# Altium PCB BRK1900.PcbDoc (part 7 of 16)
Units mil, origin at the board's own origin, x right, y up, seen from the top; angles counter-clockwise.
Board outline 8858.27 x 5905.51 mil, 10 copper layers (L1-TOP, L2-GND, L3-PWR, L4-GND, L5-PWR, L6-PWR, L7-GND, L8-SIG, L9-GND, L10-BOT), stack 48.824 mil thick; 456 components, 571 nets, 2296 pads, 2416 vias.
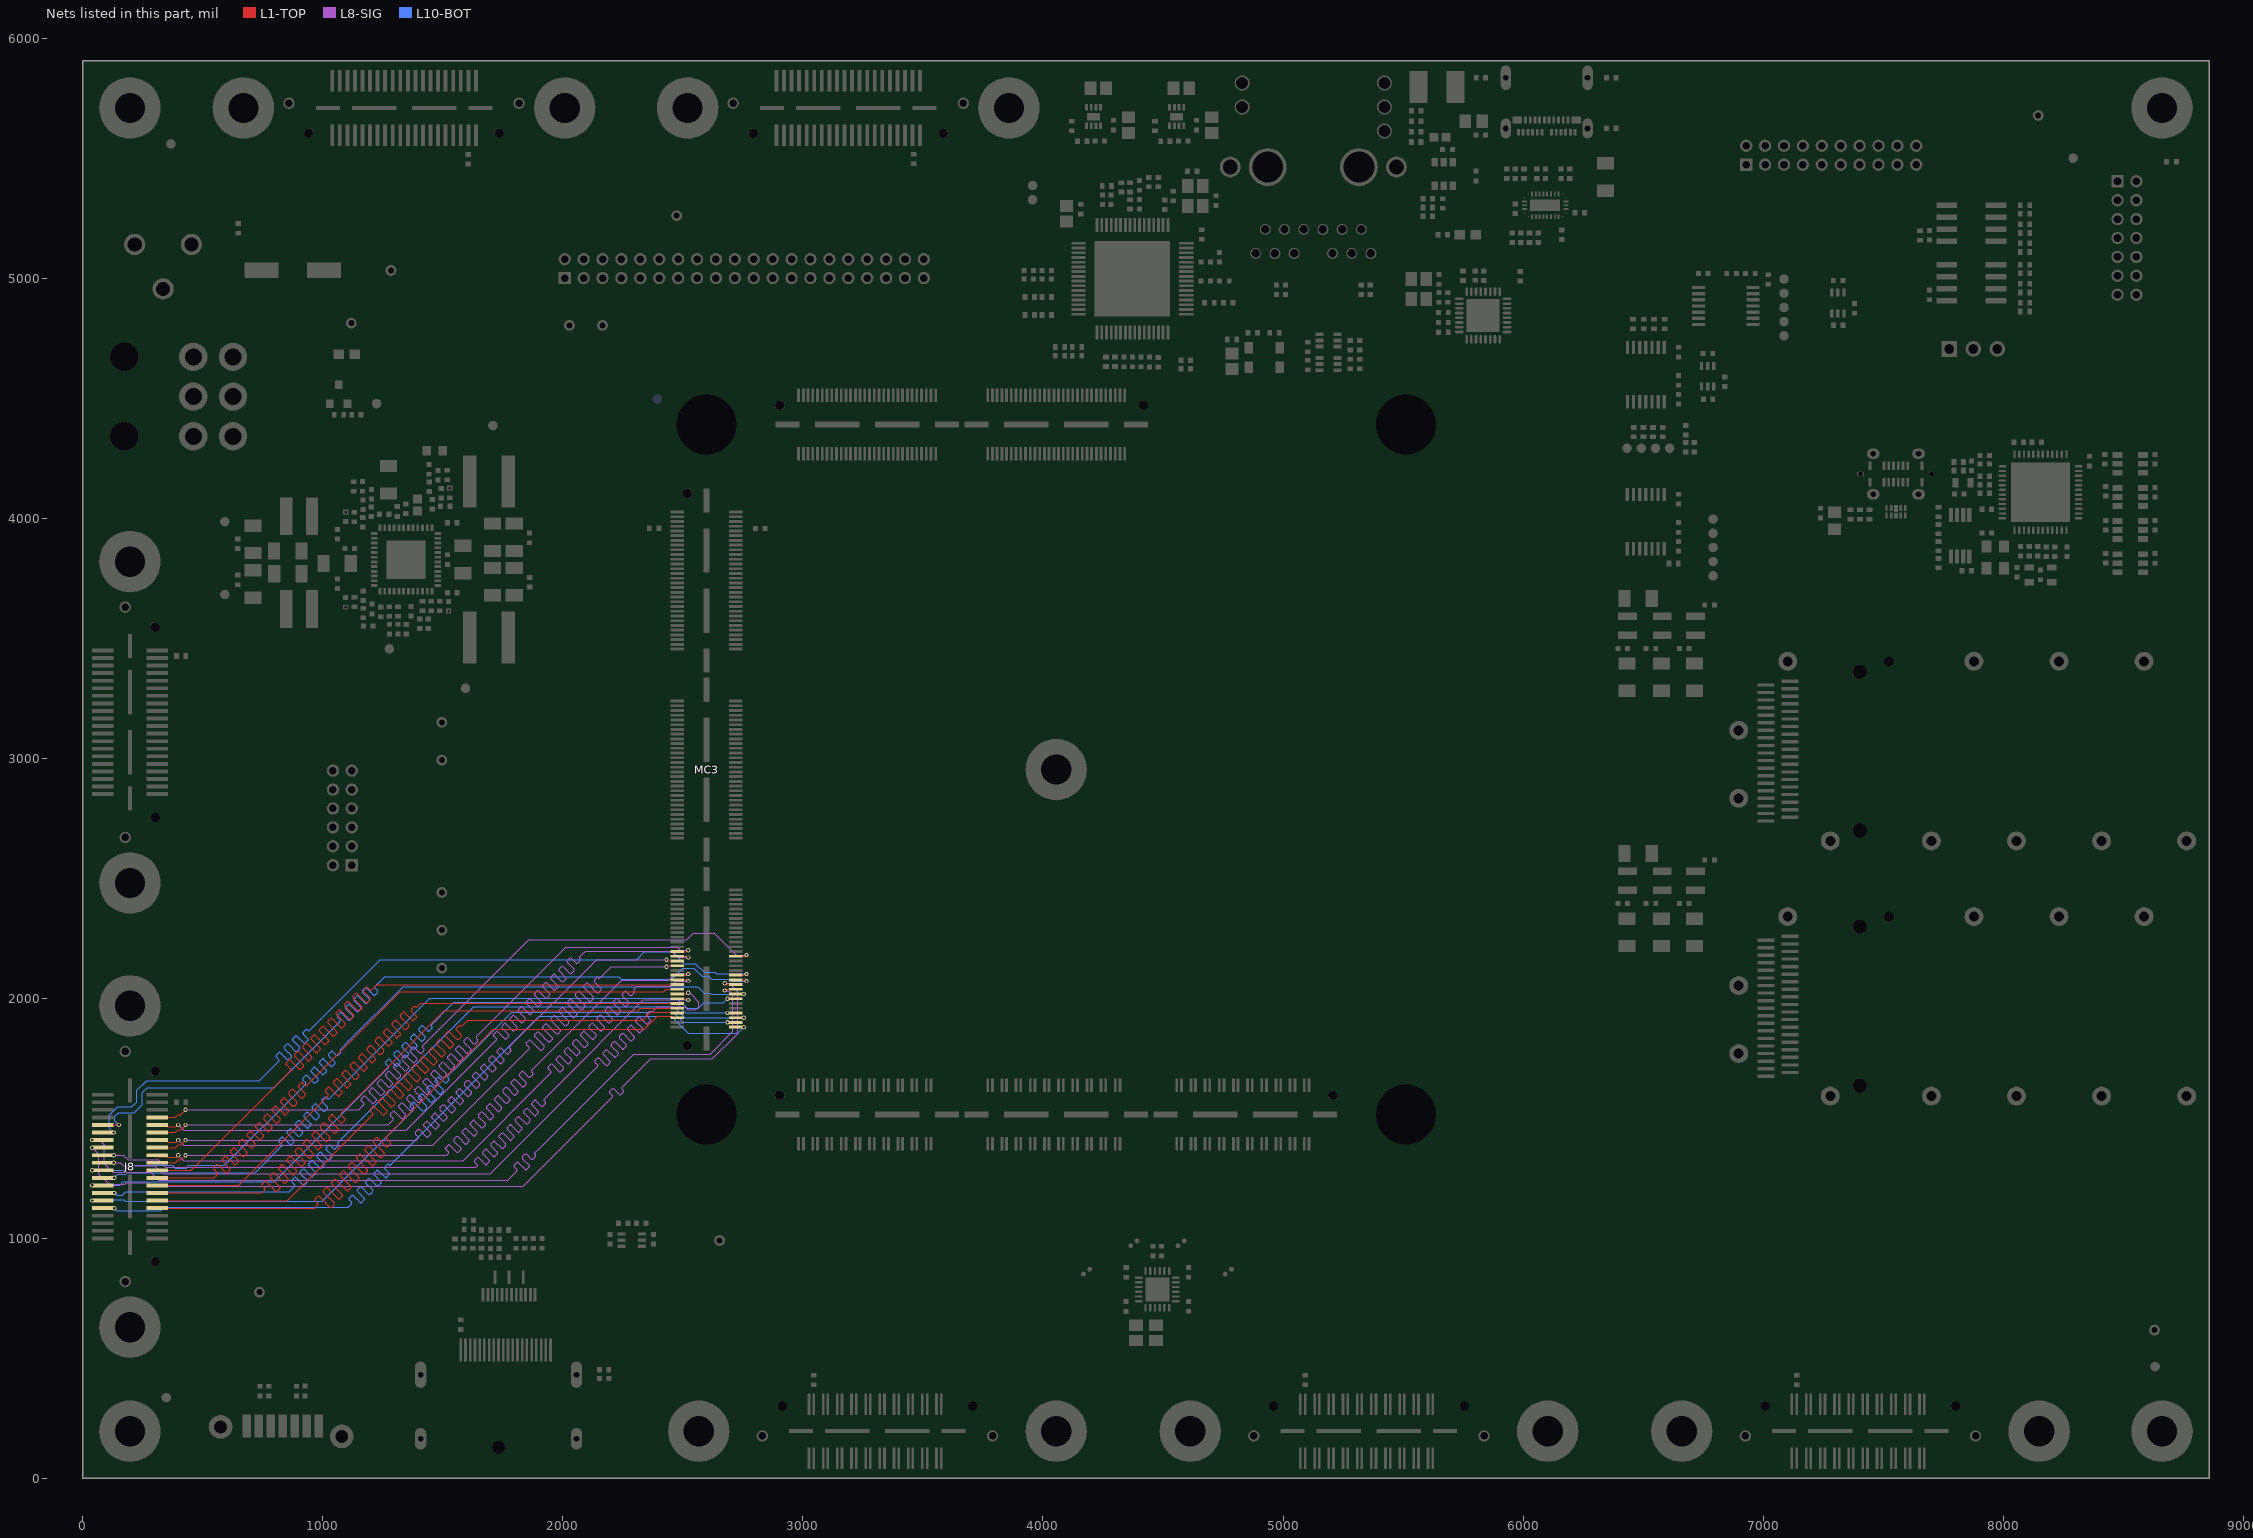
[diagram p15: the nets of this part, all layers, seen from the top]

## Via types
v1: diameter 18, hole 10, L1-TOP to L10-BOT, tented both sides, 2170 vias
v2: diameter 20, hole 10, L1-TOP to L10-BOT, tented both sides, 246 vias

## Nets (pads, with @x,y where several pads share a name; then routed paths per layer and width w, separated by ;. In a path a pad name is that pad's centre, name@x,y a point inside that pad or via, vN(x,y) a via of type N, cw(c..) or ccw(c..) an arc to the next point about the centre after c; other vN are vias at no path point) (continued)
SZG_PORTA_S3: J8.8 MC3.32 | length 3481.2
  L1-TOP w4.55: J8.8@309.65,1504.01 386.17,1504.01 397.91,1515.75 409,1515.75 428.26,1535 v1(428.26,1535.51) ; MC3.32@2720.08,2175.2 2756.5,2175.2 2761.44,2180.13 v1(2765.08,2180.13)
  L8-SIG w4.05: v1(428.26,1535.51) 1149.68,1535.51 1169.29,1555.12 1170.72,1556.55 ccw(c1167.32,1559.95) 1170.72,1563.35 1159.85,1574.23 cw(c1163.25,1577.63) 1159.85,1581.03 1170.05,1591.23 cw(c1173.45,1587.83) 1176.85,1591.23 1205.41,1562.68 ccw(c1208.81,1566.08) 1212.21,1562.68 1222.41,1572.88 ccw(c1219.01,1576.29) 1222.41,1579.69 1193.86,1608.24 cw(c1197.26,1611.64) 1193.86,1615.04 1204.06,1625.25 cw(c1207.46,1621.84) 1210.87,1625.25 1239.42,1596.69 ccw(c1242.82,1600.09) 1246.22,1596.69 1256.42,1606.9 ccw(c1253.02,1610.3) 1256.42,1613.7 1227.87,1642.25 cw(c1231.27,1645.65) 1227.87,1649.05 1238.08,1659.26 cw(c1241.48,1655.86) 1244.88,1659.26 1273.43,1630.7 ccw(c1276.83,1634.11) 1280.23,1630.7 1290.44,1640.91 ccw(c1287.04,1644.31) 1290.44,1647.71 1261.88,1676.26 cw(c1265.28,1679.66) 1261.88,1683.07 1272.09,1693.27 cw(c1275.49,1689.87) 1278.89,1693.27 1307.44,1664.72 ccw(c1310.84,1668.12) 1314.24,1664.72 1324.45,1674.92 ccw(c1321.05,1678.32) 1324.45,1681.72 1295.9,1710.28 cw(c1299.3,1713.68) 1295.9,1717.08 1306.1,1727.28 cw(c1309.5,1723.88) 1312.9,1727.28 1341.45,1698.73 ccw(c1344.86,1702.13) 1348.26,1698.73 1358.46,1708.93 ccw(c1355.06,1712.33) 1358.46,1715.73 1329.91,1744.29 cw(c1333.31,1747.69) 1329.91,1751.09 1340.11,1761.29 cw(c1343.51,1757.89) 1346.91,1761.29 1375.47,1732.74 ccw(c1378.87,1736.14) 1382.27,1732.74 1392.47,1742.94 ccw(c1389.07,1746.34) 1392.47,1749.75 1363.92,1778.3 cw(c1367.32,1781.7) 1363.92,1785.1 1374.12,1795.3 cw(c1377.52,1791.9) 1380.93,1795.3 1404.18,1772.05 ccw(c1407.58,1775.45) 1410.98,1772.05 1421.18,1782.26 ccw(c1417.78,1785.66) 1421.18,1789.06 1415.61,1794.63 cw(c1419.01,1798.03) 1415.61,1801.44 1477.11,1862.94 1858.27,2244.09 2515.75,2244.09 2542.65,2271 2630.57,2271 2721.44,2180.13 v1(2765.08,2180.13)
SZG_PORTA_S4: J8.9 MC3.22 | length 3464.4
  L1-TOP w4.55: J8.9@84.05,1472.51 84.12,1472.44 v1(149.61,1472.44) ; MC3.22@2720.08,2076.77 2756.4,2076.77 2761.44,2071.74 v1(2765.08,2071.74)
  L10-BOT w4.55: v1(149.61,1472.44) 133.86,1488.19 133.86,1507.87 149.61,1523.62 214.51,1523.62 248.03,1557.14 248.03,1606.3 269.75,1628.01 796.32,1628.01 1070.37,1902.07 1071.98,1903.68 ccw(c1068.51,1907.15) 1071.98,1910.62 1061.25,1921.35 cw(c1064.72,1924.83) 1061.25,1928.3 1071.66,1938.71 cw(c1075.14,1935.24) 1078.61,1938.71 1107.02,1910.3 ccw(c1110.49,1913.77) 1113.96,1910.3 1124.38,1920.72 ccw(c1120.91,1924.19) 1124.38,1927.66 1095.97,1956.07 cw(c1099.44,1959.54) 1095.97,1963.02 1106.38,1973.43 cw(c1109.86,1969.96) 1113.33,1973.43 1141.74,1945.02 ccw(c1145.21,1948.49) 1148.68,1945.02 1159.1,1955.44 ccw(c1155.63,1958.91) 1159.1,1962.38 1130.69,1990.79 cw(c1134.16,1994.26) 1130.69,1997.74 1141.1,2008.15 cw(c1144.57,2004.68) 1148.05,2008.15 1176.46,1979.74 ccw(c1179.93,1983.21) 1183.4,1979.74 1193.82,1990.16 ccw(c1190.35,1993.63) 1193.82,1997.1 1165.41,2025.51 cw(c1168.88,2028.98) 1165.41,2032.45 1175.82,2042.87 cw(c1179.29,2039.4) 1182.77,2042.87 1210.98,2014.66 ccw(c1214.45,2018.13) 1217.92,2014.66 1228.34,2025.07 ccw(c1224.87,2028.54) 1228.34,2032.02 1217.8,2042.55 cw(c1221.27,2046.02) 1217.8,2049.5 1255.41,2087.11 1258.86,2090.55 2232.28,2090.55 2244.09,2078.74 2452.76,2078.74 2500,2125.98 2545.72,2125.98 2580.92,2090.79 2607.32,2090.79 2618.96,2079.14 2696.45,2079.14 2703.86,2071.74 v1(2765.08,2071.74)
SZG_PORTA_S5: J8.10 MC3.31 | length 3483.8
  L1-TOP w4.55: J8.10@309.65,1472.51 315.38,1466.79 352.13,1466.79 355,1463.91 389.63,1463.91 v1(398.23,1472.51) ; MC3.31@2476.77,2175.2 2513.09,2175.2 2518.13,2170.16 v1(2521.77,2170.16)
  L8-SIG w4.05: v1@398.23,1472.76 420.43,1450.57 1348.2,1450.57 1721.55,1823.91 1722.98,1825.34 ccw(c1719.58,1828.74) 1722.98,1832.15 1712.11,1843.02 cw(c1715.51,1846.42) 1712.11,1849.82 1722.31,1860.03 cw(c1725.71,1856.63) 1729.11,1860.03 1757.67,1831.47 ccw(c1761.07,1834.88) 1764.47,1831.47 1774.67,1841.68 ccw(c1771.27,1845.08) 1774.67,1848.48 1746.12,1877.03 cw(c1749.52,1880.43) 1746.12,1883.84 1756.32,1894.04 cw(c1759.72,1890.64) 1763.12,1894.04 1791.68,1865.49 ccw(c1795.08,1868.89) 1798.48,1865.49 1808.68,1875.69 ccw(c1805.28,1879.09) 1808.68,1882.49 1780.13,1911.05 cw(c1783.53,1914.45) 1780.13,1917.85 1790.33,1928.05 cw(c1793.73,1924.65) 1797.14,1928.05 1825.69,1899.5 ccw(c1829.09,1902.9) 1832.49,1899.5 1842.69,1909.7 ccw(c1839.29,1913.1) 1842.69,1916.5 1814.14,1945.06 cw(c1817.54,1948.46) 1814.14,1951.86 1824.35,1962.06 cw(c1827.75,1958.66) 1831.15,1962.06 1859.7,1933.51 ccw(c1863.1,1936.91) 1866.5,1933.51 1876.71,1943.71 ccw(c1873.31,1947.11) 1876.71,1950.52 1848.15,1979.07 cw(c1851.55,1982.47) 1848.15,1985.87 1858.36,1996.07 cw(c1861.76,1992.67) 1865.16,1996.07 1893.71,1967.52 ccw(c1897.11,1970.92) 1900.51,1967.52 1910.72,1977.73 ccw(c1907.32,1981.13) 1910.72,1984.53 1882.17,2013.08 cw(c1885.57,2016.48) 1882.17,2019.88 1892.37,2030.09 cw(c1895.77,2026.69) 1899.17,2030.09 1927.72,2001.53 ccw(c1931.13,2004.93) 1934.53,2001.53 1944.73,2011.74 ccw(c1941.33,2015.14) 1944.73,2018.54 1916.18,2047.09 cw(c1919.58,2050.49) 1916.18,2053.89 1926.38,2064.1 cw(c1929.78,2060.7) 1933.18,2064.1 1961.74,2035.55 ccw(c1965.14,2038.95) 1968.54,2035.55 1978.74,2045.75 ccw(c1975.34,2049.15) 1978.74,2052.55 1950.19,2081.1 cw(c1953.59,2084.51) 1950.19,2087.91 1960.39,2098.11 cw(c1963.79,2094.71) 1967.19,2098.11 1995.75,2069.56 ccw(c1999.15,2072.96) 2002.55,2069.56 2012.75,2079.76 ccw(c2009.35,2083.16) 2012.75,2086.56 1984.2,2115.12 cw(c1987.6,2118.52) 1984.2,2121.92 1994.4,2132.12 cw(c1997.81,2128.72) 2001.21,2132.12 2029.76,2103.57 ccw(c2033.16,2106.97) 2036.56,2103.57 2046.77,2113.77 ccw(c2043.36,2117.17) 2046.77,2120.57 2018.21,2149.13 cw(c2021.61,2152.53) 2018.21,2155.93 2028.42,2166.13 cw(c2031.82,2162.73) 2035.22,2166.13 2054.86,2146.49 ccw(c2058.26,2149.89) 2061.66,2146.49 2071.87,2156.69 ccw(c2068.47,2160.1) 2071.87,2163.5 2069.9,2165.46 cw(c2073.3,2168.86) 2069.9,2172.26 2082.68,2185.04 2094.49,2196.85 2452.76,2196.85 2479.45,2170.16 v1(2521.77,2170.16)
SZG_PORTA_S6: J8.11 MC3.24 | length 3419.8
  L1-TOP w4.55: MC3.24@2720.08,2096.46 2756.5,2096.46 2761.44,2101.39 v1(2765.08,2101.39)
  L10-BOT w4.55: v1(128.76,1441.01) 110.24,1459.53 110.24,1511.81 145.67,1547.24 204.72,1547.24 224.41,1566.93 224.41,1616.08 265.81,1657.48 736.22,1657.48 814.96,1736.22 816.57,1737.83 ccw(c813.1,1741.3) 816.57,1744.77 805.84,1755.51 cw(c809.31,1758.98) 805.84,1762.45 816.25,1772.87 cw(c819.72,1769.39) 823.2,1772.87 851.61,1744.46 ccw(c855.08,1747.93) 858.55,1744.46 868.97,1754.87 ccw(c865.49,1758.34) 868.97,1761.81 840.55,1790.23 cw(c844.03,1793.7) 840.55,1797.17 850.97,1807.59 cw(c854.44,1804.11) 857.91,1807.59 886.33,1779.17 ccw(c889.8,1782.65) 893.27,1779.17 903.69,1789.59 ccw(c900.21,1793.06) 903.69,1796.53 875.27,1824.95 cw(c878.75,1828.42) 875.27,1831.89 885.69,1842.3 cw(c889.16,1838.83) 892.63,1842.3 921.04,1813.89 ccw(c924.52,1817.36) 927.99,1813.89 938.4,1824.31 ccw(c934.93,1827.78) 938.4,1831.25 919.08,1850.58 cw(c922.55,1854.05) 919.08,1857.52 929.49,1867.94 cw(c932.96,1864.47) 936.44,1867.94 938.09,1866.29 ccw(c941.56,1869.76) 945.03,1866.29 980.32,1901.57 1240.16,2161.42 2307.09,2161.42 2338.58,2192.91 2458.17,2192.91 2506.28,2144.8 2552.05,2144.8 2589.13,2107.72 2632.27,2107.72 2638.6,2101.39 v1(2765.08,2101.39)
SZG_PORTA_S7: J8.12 MC3.33 | length 3480.9
  L1-TOP w4.55: J8.12@309.65,1441.01 386.17,1441.01 397.91,1452.75 409,1452.75 428.26,1472 v1(428.26,1472.51) ; MC3.33@2476.77,2194.88 2513.19,2194.88 2518.13,2199.82 v1(2521.77,2199.82)
  L8-SIG w4.05: v1@428.26,1472.76 1271.97,1472.76 1291.34,1492.13 1292.77,1493.56 ccw(c1289.37,1496.96) 1292.77,1500.36 1281.9,1511.24 cw(c1285.3,1514.64) 1281.9,1518.04 1292.1,1528.24 cw(c1295.5,1524.84) 1298.9,1528.24 1327.45,1499.69 ccw(c1330.86,1503.09) 1334.26,1499.69 1344.46,1509.89 ccw(c1341.06,1513.29) 1344.46,1516.69 1315.91,1545.25 cw(c1319.31,1548.65) 1315.91,1552.05 1326.11,1562.25 cw(c1329.51,1558.85) 1332.91,1562.25 1361.47,1533.7 ccw(c1364.87,1537.1) 1368.27,1533.7 1378.47,1543.9 ccw(c1375.07,1547.31) 1378.47,1550.71 1349.92,1579.26 cw(c1353.32,1582.66) 1349.92,1586.06 1360.12,1596.27 cw(c1363.52,1592.86) 1366.93,1596.27 1395.48,1567.71 ccw(c1398.88,1571.11) 1402.28,1567.71 1412.48,1577.92 ccw(c1409.08,1581.32) 1412.48,1584.72 1383.93,1613.27 cw(c1387.33,1616.67) 1383.93,1620.07 1394.13,1630.28 cw(c1397.54,1626.88) 1400.94,1630.28 1429.49,1601.72 ccw(c1432.89,1605.13) 1436.29,1601.72 1446.5,1611.93 ccw(c1443.09,1615.33) 1446.5,1618.73 1417.94,1647.28 cw(c1421.34,1650.68) 1417.94,1654.09 1428.15,1664.29 cw(c1431.55,1660.89) 1434.95,1664.29 1463.5,1635.74 ccw(c1466.9,1639.14) 1470.3,1635.74 1480.51,1645.94 ccw(c1477.11,1649.34) 1480.51,1652.74 1451.95,1681.3 cw(c1455.36,1684.7) 1451.95,1688.1 1462.16,1698.3 cw(c1465.56,1694.9) 1468.96,1698.3 1497.51,1669.75 ccw(c1500.91,1673.15) 1504.32,1669.75 1514.52,1679.95 ccw(c1511.12,1683.35) 1514.52,1686.75 1485.97,1715.31 cw(c1489.37,1718.71) 1485.97,1722.11 1496.17,1732.31 cw(c1499.57,1728.91) 1502.97,1732.31 1531.53,1703.76 ccw(c1534.93,1707.16) 1538.33,1703.76 1548.53,1713.96 ccw(c1545.13,1717.36) 1548.53,1720.77 1519.98,1749.32 cw(c1523.38,1752.72) 1519.98,1756.12 1530.18,1766.32 cw(c1533.58,1762.92) 1536.98,1766.32 1565.54,1737.77 ccw(c1568.94,1741.17) 1572.34,1737.77 1582.54,1747.98 ccw(c1579.14,1751.38) 1582.54,1754.78 1553.99,1783.33 cw(c1557.39,1786.73) 1553.99,1790.13 1564.19,1800.34 cw(c1567.59,1796.94) 1571,1800.34 1599.55,1771.78 ccw(c1602.95,1775.18) 1606.35,1771.78 1616.56,1781.99 ccw(c1613.15,1785.39) 1616.56,1788.79 1588,1817.34 cw(c1591.4,1820.74) 1588,1824.14 1598.21,1834.35 cw(c1601.61,1830.95) 1605.01,1834.35 1627.69,1811.67 ccw(c1631.09,1815.07) 1634.49,1811.67 1644.69,1821.87 ccw(c1641.29,1825.27) 1644.69,1828.68 1639.69,1833.68 cw(c1643.09,1837.08) 1639.69,1840.48 1674.05,1874.84 2011.81,2212.6 2476.38,2212.6 2489.16,2199.82 v1(2521.77,2199.82)
SZG_PORTA_S8: J8.13 MC3.18 | length 3436.5
  L1-TOP w4.55: v1(2675.08,2032.36) 2678.72,2032.36 2683.75,2037.4 MC3.18@2720.08,2037.4
  L8-SIG w4.05: v1(39.35,1409.52) 70.8,1409.51 90.55,1389.76 90.55,1311.02 125.98,1275.59 283.46,1275.59 316.57,1242.48 1770.04,1242.48 1807.09,1279.53 1808.52,1280.96 ccw(c1805.12,1284.36) 1808.52,1287.76 1797.64,1298.64 cw(c1801.04,1302.04) 1797.64,1305.44 1807.85,1315.64 cw(c1811.25,1312.24) 1814.65,1315.64 1843.2,1287.09 ccw(c1846.6,1290.49) 1850,1287.09 1860.21,1297.29 ccw(c1856.81,1300.7) 1860.21,1304.1 1831.66,1332.65 cw(c1835.06,1336.05) 1831.66,1339.45 1841.86,1349.66 cw(c1845.26,1346.25) 1848.66,1349.66 1868.28,1330.04 ccw(c1871.68,1333.44) 1875.08,1330.04 1885.28,1340.24 ccw(c1881.88,1343.64) 1885.29,1347.04 1883.34,1348.98 cw(c1886.75,1352.38) 1883.34,1355.79 1902.96,1375.4 2295.28,1767.72 2614.17,1767.72 2708.66,1862.2 2708.66,2015.75 2692.04,2032.36 v1(2675.08,2032.36)
SZG_PORTA_S9: J8.14 MC3.27 | length 3483.8
  L1-TOP w4.55: J8.14@309.65,1409.51 315.38,1403.79 352.13,1403.79 355,1400.91 389.63,1400.91 v1(398.23,1409.51) ; v1(2431.77,2130.79) 2435.41,2130.79 2440.45,2135.83 MC3.27@2476.77,2135.83
  L8-SIG w4.05: v1(398.23,1409.51) 420.43,1387.31 1457.27,1387.31 1612.31,1542.35 1857.94,1787.98 1859.37,1789.41 ccw(c1855.97,1792.81) 1859.37,1796.21 1848.49,1807.09 cw(c1851.89,1810.49) 1848.49,1813.89 1858.7,1824.09 cw(c1862.1,1820.69) 1865.5,1824.09 1905.07,1784.52 ccw(c1908.47,1787.93) 1911.87,1784.52 1922.07,1794.73 ccw(c1918.67,1798.13) 1922.07,1801.53 1882.51,1841.1 cw(c1885.91,1844.5) 1882.51,1847.9 1892.71,1858.1 cw(c1896.11,1854.7) 1899.51,1858.1 1939.08,1818.54 ccw(c1942.48,1821.94) 1945.88,1818.54 1956.08,1828.74 ccw(c1952.68,1832.14) 1956.08,1835.54 1916.52,1875.11 cw(c1919.92,1878.51) 1916.52,1881.91 1926.72,1892.12 cw(c1930.12,1888.71) 1933.52,1892.12 1973.09,1852.55 ccw(c1976.49,1855.95) 1979.89,1852.55 1990.1,1862.75 ccw(c1986.7,1866.15) 1990.1,1869.55 1950.53,1909.12 cw(c1953.93,1912.52) 1950.53,1915.92 1960.73,1926.13 cw(c1964.13,1922.73) 1967.54,1926.13 2007.1,1886.56 ccw(c2010.5,1889.96) 2013.9,1886.56 2024.11,1896.76 ccw(c2020.71,1900.16) 2024.11,1903.57 1984.54,1943.13 cw(c1987.94,1946.53) 1984.54,1949.94 1994.74,1960.14 cw(c1998.15,1956.74) 2001.55,1960.14 2041.11,1920.57 ccw(c2044.52,1923.97) 2047.92,1920.57 2058.12,1930.77 ccw(c2054.72,1934.18) 2058.12,1937.58 2018.55,1977.14 cw(c2021.95,1980.55) 2018.55,1983.95 2028.76,1994.15 cw(c2032.16,1990.75) 2035.56,1994.15 2075.13,1954.58 ccw(c2078.53,1957.98) 2081.93,1954.58 2092.13,1964.79 ccw(c2088.73,1968.19) 2092.13,1971.59 2052.56,2011.16 cw(c2055.97,2014.56) 2052.56,2017.96 2062.77,2028.16 cw(c2066.17,2024.76) 2069.57,2028.16 2109.14,1988.59 ccw(c2112.54,1992) 2115.94,1988.6 2126.14,1998.8 ccw(c2122.74,2002.2) 2126.14,2005.6 2086.58,2045.17 cw(c2089.98,2048.57) 2086.58,2051.97 2096.78,2062.17 cw(c2100.18,2058.77) 2103.58,2062.17 2141.8,2023.96 ccw(c2145.2,2027.36) 2148.6,2023.96 2158.8,2034.16 ccw(c2155.4,2037.57) 2158.8,2040.97 2131.46,2068.31 cw(c2134.86,2071.71) 2131.46,2075.11 2141.67,2085.31 cw(c2145.07,2081.91) 2148.47,2085.31 ccw(c2151.87,2088.71) 2155.27,2085.31 2192.46,2122.5 2200.75,2130.79 v1(2431.77,2130.79)
SZG_PORTA_S10: J8.15 MC3.20 | length 3436.5
  L1-TOP w4.55: v1(2675.08,2062.02) 2678.72,2062.02 2683.65,2057.09 MC3.20@2720.08,2057.09
  L8-SIG w4.05: v1(39.35,1378) 66.93,1350.43 66.93,1267.72 110.24,1224.41 174.45,1224.41 182.32,1232.28 274.02,1232.28 289.76,1216.54 1834.65,1216.54 2204.65,1586.54 2206.08,1587.97 ccw(c2202.68,1591.38) 2206.08,1594.78 2195.21,1605.65 cw(c2198.61,1609.05) 2195.21,1612.45 2205.41,1622.66 cw(c2208.81,1619.26) 2212.21,1622.66 2235.57,1599.31 ccw(c2238.97,1602.71) 2242.37,1599.31 2252.57,1609.51 ccw(c2249.17,1612.91) 2252.57,1616.31 2246.9,1621.99 cw(c2250.3,1625.39) 2246.9,1628.79 2270.6,1652.49 2366.14,1748.03 2623.33,1748.03 2728.35,1853.05 2728.35,2027.56 2693.88,2062.02 v1(2675.08,2062.02)
SZG_PORTA_S11: J8.16 MC3.29 | length 3481.2
  L1-TOP w4.55: J8.16@309.65,1378.01 386.17,1378.01 397.91,1389.75 409,1389.75 428.26,1409 v1(428.26,1409.51) ; v1(2431.77,2160.45) 2435.41,2160.45 2440.35,2155.51 MC3.29@2476.77,2155.51
  L8-SIG w4.05: v1(428.26,1409.51) 1389.82,1409.51 1395.67,1415.35 1397.1,1416.79 ccw(c1393.7,1420.19) 1397.1,1423.59 1386.23,1434.46 cw(c1389.63,1437.87) 1386.23,1441.27 1396.43,1451.47 cw(c1399.83,1448.07) 1403.23,1451.47 1431.79,1422.92 ; 1431.79,1422.92 ccw(c1435.19,1426.32) 1438.59,1422.92 ; 1438.59,1422.92 1448.79,1433.12 ccw(c1445.39,1436.52) 1448.79,1439.92 1420.24,1468.48 cw(c1423.64,1471.88) 1420.24,1475.28 1430.44,1485.48 cw(c1433.84,1482.08) 1437.24,1485.48 1465.8,1456.93 ccw(c1469.2,1460.33) 1472.6,1456.93 1482.8,1467.13 ccw(c1479.4,1470.53) 1482.8,1473.93 1454.25,1502.49 cw(c1457.65,1505.89) 1454.25,1509.29 1464.45,1519.49 cw(c1467.85,1516.09) 1471.26,1519.49 1499.81,1490.94 ccw(c1503.21,1494.34) 1506.61,1490.94 1516.81,1501.14 ccw(c1513.41,1504.55) 1516.81,1507.95 1488.26,1536.5 cw(c1491.66,1539.9) 1488.26,1543.3 1498.47,1553.51 cw(c1501.87,1550.1) 1505.27,1553.51 1533.82,1524.95 ccw(c1537.22,1528.35) 1540.62,1524.95 1550.83,1535.16 ccw(c1547.43,1538.56) 1550.83,1541.96 1522.27,1570.51 cw(c1525.67,1573.91) 1522.27,1577.31 1532.48,1587.52 cw(c1535.88,1584.12) 1539.28,1587.52 1567.83,1558.96 ccw(c1571.23,1562.37) 1574.63,1558.96 1584.84,1569.17 ccw(c1581.44,1572.57) 1584.84,1575.97 1556.29,1604.52 cw(c1559.69,1607.92) 1556.29,1611.33 1566.49,1621.53 cw(c1569.89,1618.13) 1573.29,1621.53 1601.84,1592.98 ccw(c1605.25,1596.38) 1608.65,1592.98 1618.85,1603.18 ccw(c1615.45,1606.58) 1618.85,1609.98 1590.3,1638.54 cw(c1593.7,1641.94) 1590.3,1645.34 1600.5,1655.54 cw(c1603.9,1652.14) 1607.3,1655.54 1635.86,1626.99 ccw(c1639.26,1630.39) 1642.66,1626.99 1652.86,1637.19 ccw(c1649.46,1640.59) 1652.86,1643.99 1624.31,1672.55 cw(c1627.71,1675.95) 1624.31,1679.35 1634.51,1689.55 cw(c1637.91,1686.15) 1641.31,1689.55 1669.87,1661 ccw(c1673.27,1664.4) 1676.67,1661 1686.87,1671.2 ccw(c1683.47,1674.6) 1686.87,1678.01 1658.32,1706.56 cw(c1661.72,1709.96) 1658.32,1713.36 1668.52,1723.56 cw(c1671.93,1720.16) 1675.33,1723.56 ; 1675.33,1723.56 1703.88,1695.01 ccw(c1707.28,1698.41) 1710.68,1695.01 1720.89,1705.22 ccw(c1717.48,1708.62) 1720.89,1712.02 1692.33,1740.57 cw(c1695.73,1743.97) 1692.33,1747.37 1702.54,1757.58 cw(c1705.94,1754.18) 1709.34,1757.58 1737.89,1729.02 ccw(c1741.29,1732.42) 1744.69,1729.02 1754.9,1739.23 ccw(c1751.5,1742.63) 1754.9,1746.03 1726.34,1774.58 cw(c1729.75,1777.98) 1726.34,1781.38 1736.55,1791.59 cw(c1739.95,1788.19) 1743.35,1791.59 1765.75,1769.19 ccw(c1769.15,1772.59) 1772.55,1769.19 1782.76,1779.39 ccw(c1779.35,1782.79) 1782.76,1786.2 1778.03,1790.92 cw(c1781.44,1794.32) 1778.03,1797.72 1790.14,1809.83 2140.76,2160.45 v1(2431.77,2160.45)
SZG_PORTA_S12: J8.17 MC3.13 | length 3436.5
  L1-TOP w4.55: MC3.13@2476.77,1998.03 2513.09,1998.03 2518.13,1992.99 v1(2521.77,1992.99)
  L8-SIG w4.05: v1(128.76,1346.51) 169.24,1346.51 188.98,1326.77 314.96,1326.77 346.46,1295.28 1637.8,1295.28 1641.73,1299.21 1643.16,1300.64 ccw(c1639.76,1304.05) 1643.16,1307.45 1632.29,1318.32 cw(c1635.69,1321.72) 1632.29,1325.12 1642.49,1335.33 cw(c1645.89,1331.93) 1649.3,1335.33 1676.54,1308.08 ccw(c1679.94,1311.49) 1683.34,1308.08 1693.54,1318.29 ccw(c1690.14,1321.69) 1693.54,1325.09 1666.3,1352.33 cw(c1669.7,1355.74) 1666.3,1359.14 1676.5,1369.34 cw(c1679.91,1365.94) 1683.31,1369.34 1710.55,1342.1 ccw(c1713.95,1345.5) 1717.35,1342.1 1727.56,1352.3 ccw(c1724.16,1355.7) 1727.56,1359.1 1700.31,1386.35 cw(c1703.71,1389.75) 1700.31,1393.15 1710.52,1403.35 cw(c1713.92,1399.95) 1717.32,1403.35 1744.56,1376.11 ccw(c1747.96,1379.51) 1751.36,1376.11 1761.57,1386.31 ccw(c1758.17,1389.71) 1761.57,1393.11 1734.32,1420.36 cw(c1737.73,1423.76) 1734.32,1427.16 1744.53,1437.36 cw(c1747.93,1433.96) 1751.33,1437.36 1778.57,1410.12 ccw(c1781.98,1413.52) 1785.38,1410.12 1795.58,1420.32 ccw(c1792.18,1423.73) 1795.58,1427.13 1768.34,1454.37 cw(c1771.74,1457.77) 1768.34,1461.17 1778.54,1471.38 cw(c1781.94,1467.97) 1785.34,1471.38 1812.59,1444.13 ccw(c1815.99,1447.53) 1819.39,1444.13 1829.59,1454.34 ccw(c1826.19,1457.74) 1829.59,1461.14 1802.35,1488.38 cw(c1805.75,1491.78) 1802.35,1495.18 1812.55,1505.39 cw(c1815.95,1501.99) 1819.35,1505.39 1846.6,1478.14 ccw(c1850,1481.55) 1853.4,1478.14 1863.6,1488.35 ccw(c1860.2,1491.75) 1863.6,1495.15 1836.36,1522.39 cw(c1839.76,1525.79) 1836.36,1529.2 1846.56,1539.4 cw(c1849.96,1536) 1853.37,1539.4 1880.61,1512.16 ccw(c1884.01,1515.56) 1887.41,1512.16 1897.62,1522.36 ccw(c1894.21,1525.76) 1897.62,1529.16 1870.37,1556.41 cw(c1873.77,1559.81) 1870.37,1563.21 1880.58,1573.41 cw(c1883.98,1570.01) 1887.38,1573.41 1909.67,1551.12 ccw(c1913.07,1554.52) 1916.47,1551.12 1926.67,1561.33 ccw(c1923.27,1564.73) 1926.67,1568.13 1922.06,1572.74 cw(c1925.46,1576.14) 1922.06,1579.54 1964.14,1621.62 2335.51,1992.99 v1(2521.77,1992.99)
SZG_PORTA_S13: J8.18 MC3.21 | length 3483.8
  L1-TOP w4.55: J8.18@309.65,1346.51 315.38,1340.79 352.13,1340.79 355,1337.91 389.63,1337.91 v1(398.23,1346.51) ; MC3.21@2476.77,2076.77 2513.09,2076.77 2518.13,2071.73 v1(2521.77,2071.73)
  L8-SIG w4.05: v1(398.23,1346.51) 420.43,1324.31 1584.16,1324.31 1948.26,1688.42 1949.69,1689.85 ccw(c1946.29,1693.25) 1949.69,1696.65 1938.82,1707.53 cw(c1942.22,1710.93) 1938.82,1714.33 1949.02,1724.53 cw(c1952.42,1721.13) 1955.82,1724.53 1985.33,1695.02 ccw(c1988.73,1698.42) 1992.13,1695.02 2002.34,1705.23 ccw(c1998.94,1708.63) 2002.34,1712.03 1972.83,1741.54 cw(c1976.23,1744.94) 1972.83,1748.34 1983.03,1758.55 cw(c1986.43,1755.14) 1989.83,1758.55 2019.34,1729.04 ccw(c2022.75,1732.44) 2026.15,1729.04 2036.35,1739.24 ccw(c2032.95,1742.64) 2036.35,1746.04 2006.84,1775.55 cw(c2010.24,1778.95) 2006.84,1782.35 2017.04,1792.56 cw(c2020.45,1789.16) 2023.85,1792.56 2053.36,1763.05 ccw(c2056.76,1766.45) 2060.16,1763.05 2070.36,1773.25 ccw(c2066.96,1776.65) 2070.36,1780.05 2040.85,1809.56 cw(c2044.25,1812.96) 2040.85,1816.37 2051.06,1826.57 cw(c2054.46,1823.17) 2057.86,1826.57 2087.37,1797.06 ccw(c2090.77,1800.46) 2094.17,1797.06 2104.37,1807.26 ccw(c2100.97,1810.66) 2104.37,1814.07 2074.86,1843.57 cw(c2078.27,1846.98) 2074.86,1850.38 2085.07,1860.58 cw(c2088.47,1857.18) 2091.87,1860.58 2121.38,1831.07 ccw(c2124.78,1834.47) 2128.18,1831.07 2138.39,1841.27 ccw(c2134.98,1844.68) 2138.39,1848.08 2108.88,1877.59 cw(c2112.28,1880.99) 2108.88,1884.39 2119.08,1894.59 cw(c2122.48,1891.19) 2125.88,1894.59 2155.39,1865.08 ccw(c2158.79,1868.48) 2162.19,1865.08 2172.4,1875.29 ccw(c2169,1878.69) 2172.4,1882.09 2142.89,1911.6 cw(c2146.29,1915) 2142.89,1918.4 2153.09,1928.6 cw(c2156.49,1925.2) 2159.89,1928.6 2189.4,1899.09 ccw(c2192.8,1902.5) 2196.21,1899.09 2206.41,1909.3 ccw(c2203.01,1912.7) 2206.41,1916.1 2176.9,1945.61 cw(c2180.3,1949.01) 2176.9,1952.41 2187.1,1962.62 cw(c2190.5,1959.22) 2193.91,1962.62 2223.42,1933.11 ccw(c2226.82,1936.51) 2230.22,1933.11 2240.42,1943.31 ccw(c2237.02,1946.71) 2240.42,1950.11 2210.91,1979.62 cw(c2214.31,1983.02) 2210.91,1986.42 2221.12,1996.63 cw(c2224.52,1993.23) 2227.92,1996.63 2257.43,1967.12 ccw(c2260.83,1970.52) 2264.23,1967.12 2274.43,1977.32 ccw(c2271.03,1980.72) 2274.43,1984.12 2247.82,2010.73 cw(c2251.22,2014.13) 2247.82,2017.54 2258.03,2027.74 cw(c2261.43,2024.34) 2264.83,2027.74 2279.61,2012.96 ccw(c2283.01,2016.36) 2286.41,2012.96 2296.61,2023.17 ccw(c2293.21,2026.57) 2296.61,2029.97 cw(c2300.01,2033.37) 2296.61,2036.77 2307.84,2048 2311.02,2051.18 2448.82,2051.18 2469.37,2071.73 v1(2521.77,2071.73)
SZG_PORTA_S14: J8.19 MC3.15 | length 3437.2
  L1-TOP w4.55: MC3.15@2476.77,2017.72 2513.19,2017.72 2518.13,2022.65 v1(2521.77,2022.65)
  L8-SIG w4.05: v1(128.76,1315.01) 157.43,1315.01 169.29,1303.15 299.21,1303.15 333.53,1268.84 1697.97,1268.84 2143.13,1714 2144.56,1715.43 ccw(c2141.16,1718.83) 2144.56,1722.23 2133.69,1733.11 cw(c2137.09,1736.51) 2133.69,1739.91 2143.89,1750.11 cw(c2147.29,1746.71) 2150.69,1750.11 2179.25,1721.56 ccw(c2182.65,1724.96) 2186.05,1721.56 2196.25,1731.76 ccw(c2192.85,1735.16) 2196.25,1738.57 2167.7,1767.12 cw(c2171.1,1770.52) 2167.7,1773.92 2177.9,1784.12 cw(c2181.3,1780.72) 2184.71,1784.12 2213.26,1755.57 ccw(c2216.66,1758.97) 2220.06,1755.57 2230.26,1765.78 ccw(c2226.86,1769.18) 2230.26,1772.58 2201.71,1801.13 cw(c2205.11,1804.53) 2201.71,1807.93 2211.91,1818.14 cw(c2215.32,1814.74) 2218.72,1818.14 2247.27,1789.58 ccw(c2250.67,1792.98) 2254.07,1789.58 2264.28,1799.79 ccw(c2260.88,1803.19) 2264.28,1806.59 2235.72,1835.14 cw(c2239.12,1838.54) 2235.72,1841.94 2245.93,1852.15 cw(c2249.33,1848.75) 2252.73,1852.15 2281.28,1823.6 ccw(c2284.68,1827) 2288.08,1823.6 2298.29,1833.8 ccw(c2294.89,1837.2) 2298.29,1840.6 2269.73,1869.15 cw(c2273.14,1872.56) 2269.73,1875.96 2279.94,1886.16 cw(c2283.34,1882.76) 2286.74,1886.16 2315.29,1857.61 ccw(c2318.7,1861.01) 2322.1,1857.61 2332.3,1867.81 ccw(c2328.9,1871.21) 2332.3,1874.61 2303.75,1903.17 cw(c2307.15,1906.57) 2303.75,1909.97 2313.95,1920.17 cw(c2317.35,1916.77) 2320.75,1920.17 2347.09,1893.84 ccw(c2350.49,1897.24) 2353.89,1893.84 2364.09,1904.04 ccw(c2360.69,1907.44) 2364.09,1910.84 2348.63,1926.3 cw(c2352.03,1929.7) 2348.63,1933.11 2358.84,1943.31 cw(c2362.24,1939.91) 2365.64,1943.31 ccw(c2369.04,1946.71) 2372.44,1943.31 2379.39,1950.25 2393.7,1964.57 2507.87,1964.57 2519.69,1952.76 2554.63,1952.76 2566.93,1965.06 2566.93,1982.99 2529.94,2019.98 2524.44,2019.98 v1(2521.77,2022.65)
SZG_PORTA_S15: J8.20 MC3.23 | length 3481.2
  L1-TOP w4.55: J8.20@309.65,1315.01 386.17,1315.01 397.91,1326.75 409,1326.75 428.26,1346 v1(428.26,1346.51) ; MC3.23@2476.77,2096.46 2513.19,2096.46 2518.13,2101.39 v1(2521.77,2101.39)
  L8-SIG w4.05: v1(428.26,1346.51) 1516.24,1346.51 1521.87,1352.14 1523.3,1353.58 ccw(c1519.9,1356.98) 1523.3,1360.38 1512.43,1371.25 cw(c1515.83,1374.65) 1512.43,1378.06 1522.63,1388.26 cw(c1526.03,1384.86) 1529.43,1388.26 1557.99,1359.71 ccw(c1561.39,1363.11) 1564.79,1359.71 1574.99,1369.91 ccw(c1571.59,1373.31) 1574.99,1376.71 1546.44,1405.27 cw(c1549.84,1408.67) 1546.44,1412.07 1556.64,1422.27 cw(c1560.05,1418.87) 1563.45,1422.27 1592,1393.72 ccw(c1595.4,1397.12) 1598.8,1393.72 1609.01,1403.92 ccw(c1605.6,1407.32) 1609.01,1410.72 1580.45,1439.28 cw(c1583.85,1442.68) 1580.45,1446.08 1590.66,1456.28 cw(c1594.06,1452.88) 1597.46,1456.28 1626.01,1427.73 ccw(c1629.41,1431.13) 1632.81,1427.73 1643.02,1437.93 ccw(c1639.62,1441.33) 1643.02,1444.74 1614.46,1473.29 cw(c1617.87,1476.69) 1614.46,1480.09 1624.67,1490.29 cw(c1628.07,1486.89) 1631.47,1490.29 1660.02,1461.74 ccw(c1663.42,1465.14) 1666.83,1461.74 1677.03,1471.95 ccw(c1673.63,1475.35) 1677.03,1478.75 1648.48,1507.3 cw(c1651.88,1510.7) 1648.48,1514.1 1658.68,1524.31 cw(c1662.08,1520.91) 1665.48,1524.31 1694.04,1495.75 ccw(c1697.44,1499.15) 1700.84,1495.75 1711.04,1505.96 ccw(c1707.64,1509.36) 1711.04,1512.76 1682.49,1541.31 cw(c1685.89,1544.71) 1682.49,1548.11 1692.69,1558.32 cw(c1696.09,1554.92) 1699.49,1558.32 1728.05,1529.77 ccw(c1731.45,1533.17) 1734.85,1529.77 1745.05,1539.97 ccw(c1741.65,1543.37) 1745.05,1546.77 1716.5,1575.32 cw(c1719.9,1578.73) 1716.5,1582.13 1726.7,1592.33 cw(c1730.1,1588.93) 1733.51,1592.33 1762.06,1563.78 ccw(c1765.46,1567.18) 1768.86,1563.78 1779.06,1573.98 ccw(c1775.66,1577.38) 1779.06,1580.78 1750.51,1609.34 cw(c1753.91,1612.74) 1750.51,1616.14 1760.72,1626.34 cw(c1764.12,1622.94) 1767.52,1626.34 1796.07,1597.79 ccw(c1799.47,1601.19) 1802.87,1597.79 1813.08,1607.99 ccw(c1809.68,1611.39) 1813.08,1614.8 1784.52,1643.35 cw(c1787.92,1646.75) 1784.52,1650.15 1794.73,1660.35 cw(c1798.13,1656.95) 1801.53,1660.35 1830.08,1631.8 ccw(c1833.48,1635.2) 1836.89,1631.8 1847.09,1642 ccw(c1843.69,1645.41) 1847.09,1648.81 1818.54,1677.36 cw(c1821.94,1680.76) 1818.54,1684.16 1828.74,1694.37 cw(c1832.14,1690.96) 1835.54,1694.37 1857.98,1671.93 ccw(c1861.38,1675.33) 1864.78,1671.93 1874.99,1682.13 ccw(c1871.59,1685.53) 1874.99,1688.93 1870.23,1693.69 cw(c1873.63,1697.1) 1870.23,1700.5 1895.9,1726.17 1897.33,1727.6 2244.53,2074.8 2440.94,2074.8 2467.54,2101.39 v1(2521.77,2101.39)
SZG_PORTA_S16: J8.21 MC3.16 | length 3378.4
  L10-BOT w4.55: v1(39.35,1283.51) 170.37,1283.51 190.86,1304 375,1304 386.47,1292.53 430.53,1292.53 442,1304 590.42,1304 926.66,1640.24 928.27,1641.85 ccw(c924.8,1645.32) 928.27,1648.8 917.53,1659.53 cw(c921.01,1663) 917.54,1666.47 927.95,1676.89 cw(c931.42,1673.42) 934.89,1676.89 963.31,1648.48 ccw(c966.78,1651.95) 970.25,1648.48 980.67,1658.89 ccw(c977.19,1662.36) 980.67,1665.84 952.25,1694.25 cw(c955.73,1697.72) 952.25,1701.19 962.67,1711.61 cw(c966.14,1708.14) 969.61,1711.61 998.02,1683.2 ccw(c1001.5,1686.67) 1004.97,1683.2 1015.38,1693.61 ccw(c1011.91,1697.08) 1015.38,1700.56 986.97,1728.97 cw(c990.44,1732.44) 986.97,1735.91 997.39,1746.33 cw(c1000.86,1742.85) 1004.33,1746.33 1032.74,1717.92 ccw(c1036.22,1721.39) 1039.69,1717.92 1050.1,1728.33 ccw(c1046.63,1731.8) 1050.1,1735.27 1024.57,1760.81 cw(c1028.04,1764.28) 1024.57,1767.75 1034.99,1778.17 cw(c1038.46,1774.69) 1041.93,1778.17 1056.73,1763.37 ccw(c1060.2,1766.84) 1063.67,1763.37 1074.09,1773.78 ccw(c1070.62,1777.25) 1074.09,1780.73 cw(c1077.56,1784.2) 1074.09,1787.67 1113.19,1826.77 1334.42,2048 2561.19,2048 2588.19,2021 2612.86,2021 2617.86,2016 2752.36,2016 v1(2754.08,2017.72)
SZG_PORTA_S17: J8.22 MC3.19 | length 3558.6
  L1-TOP w4.55: J8.22@309.65,1283.51 451.82,1283.51 865.12,1696.81 866.73,1698.42 ccw(c863.26,1701.89) 866.73,1705.37 847.68,1724.41 cw(c851.15,1727.88) 847.68,1731.36 858.1,1741.77 cw(c861.57,1738.3) 865.04,1741.77 901.77,1705.05 ccw(c905.24,1708.52) 908.71,1705.05 919.12,1715.46 ccw(c915.65,1718.93) 919.12,1722.41 882.4,1759.13 cw(c885.87,1762.6) 882.4,1766.07 892.82,1776.49 cw(c896.29,1773.02) 899.76,1776.49 936.48,1739.77 ccw(c939.96,1743.24) 943.43,1739.77 953.84,1750.18 ccw(c950.37,1753.65) 953.84,1757.13 917.12,1793.85 cw(c920.59,1797.32) 917.12,1800.79 927.54,1811.21 cw(c931.01,1807.74) 934.48,1811.21 971.2,1774.48 ccw(c974.68,1777.96) 978.15,1774.48 988.56,1784.9 ccw(c985.09,1788.37) 988.56,1791.84 951.84,1828.57 cw(c955.31,1832.04) 951.84,1835.51 962.25,1845.93 cw(c965.73,1842.46) 969.2,1845.93 1005.92,1809.2 ccw(c1009.39,1812.68) 1012.87,1809.2 1023.28,1819.62 ccw(c1019.81,1823.09) 1023.28,1826.56 986.56,1863.29 cw(c990.03,1866.76) 986.56,1870.23 996.97,1880.65 cw(c1000.45,1877.17) 1003.92,1880.65 1040.64,1843.92 ccw(c1044.11,1847.39) 1047.58,1843.92 1058,1854.34 ccw(c1054.53,1857.81) 1058,1861.28 1021.28,1898.01 cw(c1024.75,1901.48) 1021.28,1904.95 1031.69,1915.37 cw(c1035.16,1911.89) 1038.64,1915.37 1075.36,1878.64 ccw(c1078.83,1882.11) 1082.3,1878.64 1092.72,1889.06 ccw(c1089.25,1892.53) 1092.72,1896 1056,1932.72 cw(c1059.47,1936.2) 1056,1939.67 1066.41,1950.08 cw(c1069.88,1946.61) 1073.36,1950.08 1110.08,1913.36 ccw(c1113.55,1916.83) 1117.02,1913.36 1127.44,1923.78 ccw(c1123.97,1927.25) 1127.44,1930.72 1090.71,1967.44 cw(c1094.19,1970.92) 1090.71,1974.39 1101.13,1984.8 cw(c1104.6,1981.33) 1108.07,1984.8 1144.8,1948.08 ccw(c1148.27,1951.55) 1151.74,1948.08 1162.16,1958.5 ccw(c1158.69,1961.97) 1162.16,1965.44 1125.43,2002.16 cw(c1128.91,2005.63) 1125.43,2009.11 1135.85,2019.52 cw(c1139.32,2016.05) 1142.79,2019.52 1179.52,1982.8 ccw(c1182.99,1986.27) 1186.46,1982.8 1196.88,1993.21 ccw(c1193.4,1996.69) 1196.88,2000.16 1170.68,2026.36 cw(c1174.15,2029.83) 1170.68,2033.3 1181.09,2043.72 cw(c1184.56,2040.25) 1188.03,2043.72 1196.56,2035.2 ccw(c1200.03,2038.67) 1203.5,2035.2 1223.17,2054.86 1225.39,2057.09 MC3.19@2476.77,2057.09
SZG_PORTA_S18: J8.23 MC3.14 | length 3381.8
  L10-BOT w4.55: v1(132.05,1252.01) 146.36,1266.32 179.63,1266.32 187.31,1274 717.9,1274 826.77,1382.87 828.38,1384.48 ccw(c824.91,1387.95) 828.38,1391.43 817.65,1402.16 cw(c821.12,1405.63) 817.65,1409.1 828.06,1419.52 cw(c831.53,1416.05) 835.01,1419.52 863.42,1391.11 ccw(c866.89,1394.58) 870.36,1391.11 880.78,1401.52 ccw(c877.31,1405) 880.78,1408.47 852.37,1436.88 cw(c855.84,1440.35) 852.37,1443.82 862.78,1454.24 cw(c866.25,1450.77) 869.73,1454.24 898.14,1425.83 ccw(c901.61,1429.3) 905.08,1425.83 915.5,1436.24 ccw(c912.02,1439.72) 915.5,1443.19 887.08,1471.6 cw(c890.56,1475.07) 887.08,1478.54 897.5,1488.96 cw(c900.97,1485.49) 904.44,1488.96 932.86,1460.55 ccw(c936.33,1464.02) 939.8,1460.55 950.22,1470.96 ccw(c946.74,1474.43) 950.22,1477.91 921.8,1506.32 cw(c925.28,1509.79) 921.8,1513.26 932.22,1523.68 cw(c935.69,1520.21) 939.16,1523.68 967.57,1495.27 ccw(c971.05,1498.74) 974.52,1495.27 984.93,1505.68 ccw(c981.46,1509.15) 984.93,1512.63 956.52,1541.04 cw(c959.99,1544.51) 956.52,1547.98 966.94,1558.4 cw(c970.41,1554.92) 973.88,1558.4 1002.29,1529.98 ccw(c1005.77,1533.46) 1009.24,1529.98 1019.65,1540.4 ccw(c1016.18,1543.87) 1019.65,1547.34 996.96,1570.04 cw(c1000.43,1573.51) 996.96,1576.98 1007.37,1587.4 cw(c1010.85,1583.93) 1014.32,1587.4 1019.33,1582.38 ccw(c1022.81,1585.85) 1026.28,1582.38 1047.04,1603.15 1444.9,2001 2474.84,2001 2517.65,1958.18 2564.48,1958.18 2587.3,1981 2669.05,1981 v1(2686.08,1998.03)
SZG_PORTA_S19: J8.24 MC3.17 | length 3558.6
  L1-TOP w4.55: J8.24@309.65,1252.01 546.3,1252.01 559.55,1265.26 561.16,1266.86 ccw(c557.68,1270.34) 561.16,1273.81 546.35,1288.61 cw(c549.82,1292.09) 546.35,1295.56 556.77,1305.97 cw(c560.24,1302.5) 563.71,1305.97 596.19,1273.49 ccw(c599.67,1276.96) 603.14,1273.49 613.55,1283.91 ccw(c610.08,1287.38) 613.55,1290.85 581.07,1323.33 cw(c584.54,1326.8) 581.07,1330.28 591.49,1340.69 cw(c594.96,1337.22) 598.43,1340.69 630.91,1308.21 ccw(c634.38,1311.68) 637.86,1308.21 648.27,1318.63 ccw(c644.8,1322.1) 648.27,1325.57 615.79,1358.05 cw(c619.26,1361.52) 615.79,1365 626.2,1375.41 cw(c629.68,1371.94) 633.15,1375.41 665.63,1342.93 ccw(c669.1,1346.4) 672.57,1342.93 682.99,1353.34 ccw(c679.52,1356.82) 682.99,1360.29 650.51,1392.77 cw(c653.98,1396.24) 650.51,1399.71 660.92,1410.13 cw(c664.4,1406.66) 667.87,1410.13 700.35,1377.65 ccw(c703.82,1381.12) 707.29,1377.65 717.71,1388.06 ccw(c714.24,1391.54) 717.71,1395.01 685.23,1427.49 ; 685.23,1434.43 695.64,1444.85 cw(c699.11,1441.38) 702.59,1444.85 735.07,1412.37 ccw(c738.54,1415.84) 742.01,1412.37 752.43,1422.78 ccw(c748.96,1426.25) 752.43,1429.73 719.95,1462.21 cw(c723.42,1465.68) 719.95,1469.15 730.36,1479.57 cw(c733.83,1476.1) 737.31,1479.57 769.79,1447.09 ccw(c773.26,1450.56) 776.73,1447.09 787.15,1457.5 ccw(c783.68,1460.97) 787.15,1464.44 754.66,1496.93 cw(c758.14,1500.4) 754.66,1503.87 765.08,1514.29 cw(c768.55,1510.82) 772.02,1514.29 804.51,1481.8 ccw(c807.98,1485.28) 811.45,1481.8 821.87,1492.22 ccw(c818.39,1495.69) 821.87,1499.16 789.38,1531.65 cw(c792.86,1535.12) 789.38,1538.59 799.8,1549.01 cw(c803.27,1545.53) 806.74,1549.01 839.23,1516.52 ccw(c842.7,1520) 846.17,1516.52 856.59,1526.94 ccw(c853.11,1530.41) 856.59,1533.88 824.1,1566.37 cw(c827.57,1569.84) 824.1,1573.31 834.52,1583.72 cw(c837.99,1580.25) 841.46,1583.73 873.94,1551.24 ccw(c877.42,1554.71) 880.89,1551.24 891.3,1561.66 ccw(c887.83,1565.13) 891.3,1568.6 858.82,1601.08 cw(c862.29,1604.56) 858.82,1608.03 869.24,1618.44 cw(c872.71,1614.97) 876.18,1618.44 908.66,1585.96 ccw(c912.14,1589.43) 915.61,1585.96 926.02,1596.38 ccw(c922.55,1599.85) 926.02,1603.32 899.83,1629.51 cw(c903.3,1632.99) 899.83,1636.46 910.25,1646.87 cw(c913.72,1643.4) 917.19,1646.87 925.71,1638.36 ccw(c929.18,1641.83) 932.65,1638.36 982.81,1688.51 1321.85,2027.56 2419.56,2027.56 2429.4,2037.4 MC3.17@2476.77,2037.4 ; 685.23,1427.49 cw(c688.7,1430.96) 685.23,1434.43
SZG_PORTA_S20: J8.25 MC3.8 | length 3378.4
  L10-BOT w4.55: v1(39.35,1220.51) 154.51,1220.51 169,1235 797.99,1235 1270.87,1707.88 1272.48,1709.49 ccw(c1269.01,1712.96) 1272.48,1716.43 1261.74,1727.16 cw(c1265.22,1730.64) 1261.74,1734.11 1272.16,1744.52 cw(c1275.63,1741.05) 1279.1,1744.52 1304.84,1718.78 ccw(c1308.32,1722.26) 1311.79,1718.78 1322.2,1729.2 ccw(c1318.73,1732.67) 1322.2,1736.14 1296.46,1761.88 cw(c1299.94,1765.36) 1296.46,1768.83 1306.88,1779.24 cw(c1310.35,1775.77) 1313.82,1779.24 1339.56,1753.5 ccw(c1343.03,1756.98) 1346.51,1753.5 1356.92,1763.92 ccw(c1353.45,1767.39) 1356.92,1770.86 1331.18,1796.6 cw(c1334.65,1800.07) 1331.18,1803.55 1341.6,1813.96 cw(c1345.07,1810.49) 1348.54,1813.96 1374.28,1788.22 ccw(c1377.75,1791.69) 1381.23,1788.22 1391.64,1798.64 ccw(c1388.17,1802.11) 1391.64,1805.58 1365.9,1831.32 cw(c1369.37,1834.79) 1365.9,1838.26 1376.32,1848.68 cw(c1379.79,1845.21) 1383.26,1848.68 1409,1822.94 ccw(c1412.47,1826.41) 1415.94,1822.94 1426.36,1833.36 ccw(c1422.89,1836.83) 1426.36,1840.3 1400.62,1866.04 cw(c1404.09,1869.51) 1400.62,1872.98 1411.04,1883.4 cw(c1414.51,1879.93) 1417.98,1883.4 1437.28,1864.1 ccw(c1440.75,1867.57) 1444.22,1864.1 1454.64,1874.52 ccw(c1451.16,1877.99) 1454.64,1881.46 1453.02,1883.08 cw(c1456.49,1886.55) 1453.02,1890.03 1531,1968.01 1545.99,1983 2468.47,1983 2512.49,1938.98 v1(2686.08,1938.98)
SZG_PORTA_S21: J8.26 MC3.11 | length 3558.6
  L1-TOP w4.55: J8.26@309.65,1220.51 649.65,1220.51 1020.35,1591.21 1021.96,1592.82 ccw(c1018.48,1596.29) 1021.96,1599.77 1011.22,1610.5 cw(c1014.69,1613.97) 1011.22,1617.44 1021.64,1627.86 cw(c1025.11,1624.39) 1028.58,1627.86 1062.57,1593.87 ccw(c1066.04,1597.34) 1069.52,1593.87 1079.93,1604.28 ccw(c1076.46,1607.76) 1079.93,1611.23 1045.94,1645.22 cw(c1049.41,1648.69) 1045.94,1652.16 1056.36,1662.58 cw(c1059.83,1659.11) 1063.3,1662.58 1097.29,1628.59 ccw(c1100.76,1632.06) 1104.24,1628.59 1114.65,1639 ccw(c1111.18,1642.47) 1114.65,1645.95 1080.66,1679.94 cw(c1084.13,1683.41) 1080.66,1686.88 1091.08,1697.3 cw(c1094.55,1693.83) 1098.02,1697.3 1132.01,1663.31 ccw(c1135.48,1666.78) 1138.95,1663.31 1149.37,1673.72 ccw(c1145.9,1677.19) 1149.37,1680.67 1115.38,1714.66 cw(c1118.85,1718.13) 1115.38,1721.6 1125.79,1732.02 cw(c1129.27,1728.54) 1132.74,1732.02 1166.73,1698.02 ccw(c1170.2,1701.5) 1173.67,1698.02 1184.09,1708.44 ccw(c1180.62,1711.91) 1184.09,1715.38 1150.1,1749.38 cw(c1153.57,1752.85) 1150.1,1756.32 1160.51,1766.73 cw(c1163.99,1763.26) 1167.46,1766.73 1201.45,1732.74 ccw(c1204.92,1736.22) 1208.39,1732.74 1218.81,1743.16 ccw(c1215.34,1746.63) 1218.81,1750.1 1184.82,1784.09 cw(c1188.29,1787.57) 1184.82,1791.04 1195.23,1801.45 cw(c1198.7,1797.98) 1202.18,1801.45 1236.17,1767.46 ccw(c1239.64,1770.93) 1243.11,1767.46 1253.53,1777.88 ccw(c1250.06,1781.35) 1253.53,1784.82 1219.54,1818.81 cw(c1223.01,1822.29) 1219.54,1825.76 1229.95,1836.17 cw(c1233.42,1832.7) 1236.89,1836.17 1270.89,1802.18 ccw(c1274.36,1805.65) 1277.83,1802.18 1288.25,1812.6 ccw(c1284.77,1816.07) 1288.25,1819.54 1254.25,1853.53 cw(c1257.73,1857) 1254.25,1860.48 1264.67,1870.89 cw(c1268.14,1867.42) 1271.61,1870.89 1305.61,1836.9 ccw(c1309.08,1840.37) 1312.55,1836.9 1322.96,1847.32 ccw(c1319.49,1850.79) 1322.96,1854.26 1288.97,1888.25 cw(c1292.45,1891.72) 1288.97,1895.19 1299.39,1905.61 cw(c1302.86,1902.14) 1306.33,1905.61 1340.32,1871.62 ccw(c1343.8,1875.09) 1347.27,1871.62 1357.68,1882.03 ccw(c1354.21,1885.51) 1357.68,1888.98 1323.69,1922.97 cw(c1327.16,1926.44) 1323.69,1929.91 1334.11,1940.33 cw(c1337.58,1936.86) 1341.05,1940.33 1372.51,1908.87 ccw(c1375.98,1912.34) 1379.45,1908.87 1389.87,1919.29 ccw(c1386.4,1922.76) 1389.87,1926.23 1369.14,1946.96 cw(c1372.62,1950.43) 1369.14,1953.9 1379.56,1964.32 cw(c1383.03,1960.84) 1386.5,1964.32 ccw(c1389.98,1967.79) 1393.45,1964.31 1402.79,1973.65 1407.48,1978.35 MC3.11@2476.77,1978.35
SZG_PORTA_S22: J8.27 MC3.6 | length 3381.7
  L10-BOT w4.55: v1(132.05,1189.01) 132.55,1189.01 141.99,1179.57 164.59,1179.57 180.02,1195 860.35,1195 880.91,1215.55 882.51,1217.16 ccw(c879.04,1220.63) 882.51,1224.1 871.78,1234.84 cw(c875.25,1238.31) 871.78,1241.78 882.2,1252.2 cw(c885.67,1248.73) 889.14,1252.2 917.55,1223.79 ccw(c921.02,1227.26) 924.5,1223.79 934.91,1234.2 ccw(c931.44,1237.67) 934.91,1241.15 906.5,1269.56 cw(c909.97,1273.03) 906.5,1276.5 916.92,1286.92 cw(c920.39,1283.44) 923.86,1286.92 952.27,1258.5 ccw(c955.74,1261.98) 959.21,1258.5 969.63,1268.92 ccw(c966.16,1272.39) 969.63,1275.86 941.22,1304.28 cw(c944.69,1307.75) 941.22,1311.22 951.63,1321.64 cw(c955.11,1318.16) 958.58,1321.64 986.99,1293.22 ccw(c990.46,1296.7) 993.93,1293.22 1004.35,1303.64 ccw(c1000.88,1307.11) 1004.35,1310.58 975.94,1338.99 cw(c979.41,1342.47) 975.94,1345.94 986.35,1356.35 cw(c989.83,1352.88) 993.3,1356.35 1021.71,1327.94 ccw(c1025.18,1331.41) 1028.65,1327.94 1039.07,1338.36 ccw(c1035.6,1341.83) 1039.07,1345.3 1014.52,1369.85 cw(c1018,1373.32) 1014.52,1376.79 1024.94,1387.21 cw(c1028.41,1383.73) 1031.88,1387.21 1045.69,1373.39 ccw(c1049.17,1376.87) 1052.64,1373.39 1063.05,1383.81 ccw(c1059.58,1387.28) 1063.05,1390.75 cw(c1066.52,1394.23) 1063.05,1397.7 1075.38,1410.03 1629.35,1964 2463,1964 2507.71,1919.29 v1(2754.08,1919.29)
SZG_PORTA_S23: J8.28 MC3.9 | length 3558.6
  L1-TOP w4.55: J8.28@309.65,1189.01 746.1,1189.01 756.4,1199.31 758.01,1200.92 ccw(c754.53,1204.39) 758.01,1207.86 747.27,1218.6 cw(c750.74,1222.07) 747.27,1225.54 757.69,1235.96 cw(c761.16,1232.49) 764.63,1235.96 803.71,1196.87 ccw(c807.19,1200.35) 810.66,1196.87 821.07,1207.29 ccw(c817.6,1210.76) 821.07,1214.23 781.99,1253.32 cw(c785.46,1256.79) 781.99,1260.26 792.41,1270.68 cw(c795.88,1267.2) 799.35,1270.68 838.43,1231.59 ccw(c841.91,1235.07) 845.38,1231.59 855.79,1242.01 ccw(c852.32,1245.48) 855.79,1248.95 816.71,1288.04 cw(c820.18,1291.51) 816.71,1294.98 827.13,1305.4 cw(c830.6,1301.92) 834.07,1305.4 873.15,1266.31 ccw(c876.62,1269.78) 880.1,1266.31 890.51,1276.73 ccw(c887.04,1280.2) 890.51,1283.67 851.43,1322.75 cw(c854.9,1326.23) 851.43,1329.7 861.85,1340.11 cw(c865.32,1336.64) 868.79,1340.11 907.87,1301.03 ccw(c911.34,1304.5) 914.82,1301.03 925.23,1311.45 ccw(c921.76,1314.92) 925.23,1318.39 886.15,1357.47 cw(c889.62,1360.95) 886.15,1364.42 896.56,1374.83 cw(c900.04,1371.36) 903.51,1374.83 942.59,1335.75 ccw(c946.06,1339.22) 949.53,1335.75 959.95,1346.17 ccw(c956.48,1349.64) 959.95,1353.11 920.87,1392.19 cw(c924.34,1395.66) 920.87,1399.14 931.28,1409.55 cw(c934.76,1406.08) 938.23,1409.55 977.31,1370.47 ccw(c980.78,1373.94) 984.25,1370.47 994.67,1380.88 ccw(c991.2,1384.36) 994.67,1387.83 955.59,1426.91 cw(c959.06,1430.38) 955.59,1433.86 966,1444.27 cw(c969.47,1440.8) 972.95,1444.27 1012.03,1405.19 ccw(c1015.5,1408.66) 1018.97,1405.19 1029.39,1415.6 ccw(c1025.92,1419.08) 1029.39,1422.55 990.31,1461.63 cw(c993.78,1465.1) 990.31,1468.57 1000.72,1478.99 cw(c1004.19,1475.52) 1007.66,1478.99 1046.75,1439.91 ccw(c1050.22,1443.38) 1053.69,1439.91 1064.11,1450.32 ccw(c1060.64,1453.79) 1064.11,1457.27 1025.02,1496.35 cw(c1028.5,1499.82) 1025.02,1503.29 1035.44,1513.71 cw(c1038.91,1510.24) 1042.38,1513.71 1074.79,1481.3 ccw(c1078.26,1484.77) 1081.74,1481.3 1092.15,1491.72 ccw(c1088.68,1495.19) 1092.15,1498.66 1077.42,1513.39 cw(c1080.89,1516.86) 1077.42,1520.33 1126.35,1569.26 1505.91,1948.82 2312.82,1948.82 2322.66,1958.66 MC3.9@2476.77,1958.66
SZG_PORTA_S24: J8.29 MC3.4 | length 3379.2
  L10-BOT w4.55: v1(39.35,1157.51) 56.13,1157.51 59.45,1160.83 171.17,1160.83 178,1154 998.49,1154 1373.55,1529.06 1375.16,1530.67 ccw(c1371.69,1534.14) 1375.16,1537.62 1364.43,1548.35 cw(c1367.9,1551.82) 1364.43,1555.29 1374.84,1565.71 cw(c1378.31,1562.24) 1381.79,1565.71 1415.2,1532.29 ccw(c1418.68,1535.76) 1422.15,1532.29 1432.56,1542.71 ccw(c1429.09,1546.18) 1432.56,1549.65 1399.15,1583.07 cw(c1402.62,1586.54) 1399.15,1590.01 1409.56,1600.43 cw(c1413.03,1596.96) 1416.51,1600.43 1449.92,1567.01 ccw(c1453.39,1570.48) 1456.87,1567.01 1467.28,1577.43 ccw(c1463.81,1580.9) 1467.28,1584.37 1433.86,1617.79 cw(c1437.34,1621.26) 1433.86,1624.73 1444.28,1635.15 cw(c1447.75,1631.68) 1451.22,1635.15 1484.64,1601.73 ccw(c1488.11,1605.2) 1491.59,1601.73 1502,1612.15 ccw(c1498.53,1615.62) 1502,1619.09 1468.58,1652.51 cw(c1472.06,1655.98) 1468.58,1659.45 1479,1669.87 cw(c1482.47,1666.39) 1485.94,1669.87 1507.21,1648.6 ccw(c1510.68,1652.07) 1514.15,1648.6 1524.57,1659.02 ccw(c1521.1,1662.49) 1524.57,1665.96 1520.98,1669.55 cw(c1524.45,1673.02) 1520.98,1676.49 1566.43,1721.94 1786.49,1942 2459.16,1942 2501.55,1899.61 v1(2686.08,1899.61)
SZG_PORTA_S25: J8.30 MC3.7 | length 3559.7
  L1-TOP w4.55: J8.30@309.65,1157.51 852.39,1157.51 1207.07,1512.18 1208.68,1513.79 ccw(c1205.2,1517.27) 1208.68,1520.74 1197.94,1531.47 cw(c1201.41,1534.94) 1197.94,1538.42 1208.36,1548.83 cw(c1211.83,1545.36) 1215.3,1548.83 1248.92,1515.22 ccw(c1252.39,1518.69) 1255.86,1515.22 1266.28,1525.63 ; 1266.28,1525.63 ccw(c1262.8,1529.1) 1266.28,1532.57 1232.66,1566.19 cw(c1236.13,1569.66) 1232.66,1573.13 1243.08,1583.55 cw(c1246.55,1580.08) 1250.02,1583.55 1283.64,1549.93 ccw(c1287.11,1553.41) 1290.58,1549.93 1301,1560.35 ccw(c1297.52,1563.82) 1301,1567.29 1267.38,1600.91 cw(c1270.85,1604.38) 1267.38,1607.85 1277.8,1618.27 cw(c1281.27,1614.8) 1284.74,1618.27 1318.36,1584.65 ccw(c1321.83,1588.12) 1325.3,1584.65 1335.71,1595.07 ccw(c1332.24,1598.54) 1335.71,1602.01 1302.1,1635.63 cw(c1305.57,1639.1) 1302.1,1642.57 1312.51,1652.99 cw(c1315.99,1649.52) 1319.46,1652.99 1353.07,1619.37 ccw(c1356.55,1622.84) 1360.02,1619.37 1370.43,1629.79 ccw(c1366.96,1633.26) 1370.43,1636.73 1336.82,1670.35 cw(c1340.29,1673.82) 1336.82,1677.29 1347.23,1687.71 cw(c1350.71,1684.24) 1354.18,1687.71 1387.79,1654.09 ccw(c1391.26,1657.56) 1394.74,1654.09 1405.15,1664.51 ccw(c1401.68,1667.98) 1405.15,1671.45 1371.54,1705.07 cw(c1375.01,1708.54) 1371.54,1712.01 1381.95,1722.43 cw(c1385.42,1718.95) 1388.9,1722.43 1422.51,1688.81 ccw(c1425.98,1692.28) 1429.46,1688.81 1439.87,1699.23 ccw(c1436.4,1702.7) 1439.87,1706.17 1406.26,1739.79 cw(c1409.73,1743.26) 1406.26,1746.73 1416.67,1757.14 cw(c1420.14,1753.67) 1423.62,1757.14 1457.23,1723.53 ccw(c1460.7,1727) 1464.17,1723.53 1474.59,1733.94 ccw(c1471.12,1737.42) 1474.59,1740.89 1440.97,1774.5 cw(c1444.45,1777.98) 1440.97,1781.45 1451.39,1791.86 cw(c1454.86,1788.39) 1458.33,1791.86 1491.95,1758.25 ccw(c1495.42,1761.72) 1498.89,1758.25 1509.31,1768.66 ccw(c1505.84,1772.14) 1509.31,1775.61 1475.69,1809.22 cw(c1479.17,1812.7) 1475.69,1816.17 1486.11,1826.58 cw(c1489.58,1823.11) 1493.05,1826.58 1526.67,1792.97 ccw(c1530.14,1796.44) 1533.61,1792.97 1544.03,1803.38 ccw(c1540.56,1806.85) 1544.03,1810.33 1510.41,1843.94 cw(c1513.88,1847.41) 1510.41,1850.89 1520.83,1861.3 cw(c1524.3,1857.83) 1527.77,1861.3 1558.65,1830.42 ccw(c1562.12,1833.89) 1565.6,1830.42 1576.01,1840.84 ccw(c1572.54,1844.31) 1576.01,1847.78 1555.86,1867.93 cw(c1559.34,1871.4) 1555.86,1874.87 1566.28,1885.29 cw(c1569.75,1881.82) 1573.22,1885.29 ccw(c1576.7,1888.76) 1580.17,1885.29 1593.01,1898.13 1604.33,1909.45 2332.45,1909.45 2365,1942 2473.75,1942 MC3.7@2476.77,1938.98
SZG_PORTA_S26: J8.31 MC3.2 | length 3381.7
  L10-BOT w4.55: v1(132.05,1126.01) 142.06,1116 326,1116 339,1129 1106.36,1129 1118.6,1141.24 1120.21,1142.85 ccw(c1116.74,1146.32) 1120.21,1149.79 1109.48,1160.53 cw(c1112.95,1164) 1109.48,1167.47 1119.89,1177.89 cw(c1123.37,1174.41) 1126.84,1177.89 1155.25,1149.47 ccw(c1158.72,1152.95) 1162.19,1149.47 1172.61,1159.89 ccw(c1169.14,1163.36) 1172.61,1166.83 1144.2,1195.25 cw(c1147.67,1198.72) 1144.2,1202.19 1154.61,1212.61 cw(c1158.08,1209.13) 1161.56,1212.61 1189.97,1184.19 ccw(c1193.44,1187.67) 1196.91,1184.19 1207.33,1194.61 ccw(c1203.86,1198.08) 1207.33,1201.55 1178.92,1229.96 cw(c1182.39,1233.44) 1178.92,1236.91 1189.33,1247.32 cw(c1192.8,1243.85) 1196.27,1247.32 1224.69,1218.91 ccw(c1228.16,1222.38) 1231.63,1218.91 1242.05,1229.33 ccw(c1238.57,1232.8) 1242.05,1236.27 1213.63,1264.68 cw(c1217.11,1268.16) 1213.63,1271.63 1224.05,1282.04 cw(c1227.52,1278.57) 1230.99,1282.04 1259.41,1253.63 ccw(c1262.88,1257.1) 1266.35,1253.63 1276.76,1264.05 ccw(c1273.29,1267.52) 1276.76,1270.99 1258.1,1289.66 cw(c1261.57,1293.13) 1258.1,1296.6 1268.51,1307.02 cw(c1271.98,1303.55) 1275.46,1307.02 1276.45,1306.03 ccw(c1279.92,1309.5) 1283.39,1306.03 1375.24,1397.88 1902.36,1925 2450.59,1925 2521.59,1854 2728.16,1854 v1(2754.08,1879.92)
SZG_PORTA_S27: J8.32 MC3.5 | length 3560.4
  L1-TOP w4.55: J8.32@309.65,1126.01 965.58,1126.01 977.36,1137.8 978.97,1139.4 ccw(c975.5,1142.88) 978.97,1146.35 968.24,1157.08 cw(c971.71,1160.55) 968.24,1164.03 978.65,1174.44 cw(c982.12,1170.97) 985.6,1174.44 1029.8,1130.24 ccw(c1033.27,1133.71) 1036.74,1130.24 1047.16,1140.66 ccw(c1043.69,1144.13) 1047.16,1147.6 1002.96,1191.8 cw(c1006.43,1195.27) 1002.96,1198.74 1013.37,1209.16 cw(c1016.84,1205.69) 1020.32,1209.16 1064.52,1164.96 ccw(c1067.99,1168.43) 1071.46,1164.96 1081.88,1175.37 ccw(c1078.41,1178.85) 1081.88,1182.32 1037.68,1226.52 cw(c1041.15,1229.99) 1037.68,1233.46 1048.09,1243.88 cw(c1051.56,1240.41) 1055.03,1243.88 1099.24,1199.68 ccw(c1102.71,1203.15) 1106.18,1199.68 1116.6,1210.09 ccw(c1113.12,1213.57) 1116.6,1217.04 1072.39,1261.24 cw(c1075.87,1264.71) 1072.39,1268.18 1082.81,1278.6 cw(c1086.28,1275.13) 1089.75,1278.6 1133.96,1234.4 ccw(c1137.43,1237.87) 1140.9,1234.4 1151.31,1244.81 ccw(c1147.84,1248.28) 1151.31,1251.76 1107.11,1295.96 cw(c1110.59,1299.43) 1107.11,1302.9 1117.53,1313.32 cw(c1121,1309.85) 1124.47,1313.32 1168.67,1269.12 ccw(c1172.15,1272.59) 1175.62,1269.12 1186.03,1279.53 ccw(c1182.56,1283) 1186.03,1286.47 1141.83,1330.68 cw(c1145.3,1334.15) 1141.83,1337.62 1152.25,1348.04 cw(c1155.72,1344.56) 1159.19,1348.04 1203.39,1303.83 ccw(c1206.87,1307.31) 1210.34,1303.83 1220.75,1314.25 ccw(c1217.28,1317.72) 1220.75,1321.19 1176.55,1365.4 cw(c1180.02,1368.87) 1176.55,1372.34 1186.97,1382.76 cw(c1190.44,1379.28) 1193.91,1382.76 1238.11,1338.55 ccw(c1241.58,1342.03) 1245.06,1338.55 1255.47,1348.97 ccw(c1252,1352.44) 1255.47,1355.91 1211.27,1400.11 cw(c1214.74,1403.59) 1211.27,1407.06 1221.69,1417.47 cw(c1225.16,1414) 1228.63,1417.47 1263.76,1382.35 ccw(c1267.23,1385.82) 1270.7,1382.35 1281.11,1392.76 ccw(c1277.64,1396.24) 1281.11,1399.71 1263.67,1417.16 cw(c1267.14,1420.63) 1263.67,1424.1 1294.82,1455.26 1709.65,1870.08 2338.08,1870.08 2393,1925 2448.69,1925 2454.4,1919.29 MC3.5@2476.77,1919.29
